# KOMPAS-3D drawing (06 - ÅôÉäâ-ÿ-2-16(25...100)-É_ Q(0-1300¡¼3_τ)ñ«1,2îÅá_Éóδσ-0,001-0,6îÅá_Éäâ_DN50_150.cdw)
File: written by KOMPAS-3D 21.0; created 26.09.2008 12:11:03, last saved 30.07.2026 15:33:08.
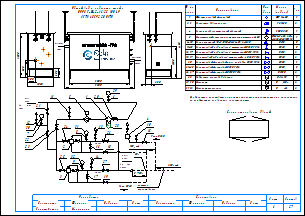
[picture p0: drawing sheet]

Sheets 1-2: A3, landscape

Document properties: Наименование: Макро:21; Автор: RaskoAdmin; Форматы листов документа: 2xA3; Полное имя файла: \\ur38nt01\Departments\КТО\КБ ПУРДГ\Заявки\Прайс-лист на типовые шкафы ГРПШ\ПУРДГ_стандарт_30_04_2026\ПУРДГ с РДГ(Н, В)\ПУРДГ-Ш-2-16(25...100)-Р_ Q(0-1300нм3_ч)до1,2МПа_Рвых-0,001-0,6МПа_РДГ_DN50_150.cdw

Title block, sheet 1: Наименование: Пункт учета газа / ПУГ-Ш-400-Р / ЛГТИ.485922.001ТУ; designation: ЛГТИ.03.4411141; sheet number: 1; Количество листов документа: 2; organisation: ООО "ЭЛЬСТЕР Газэлектроника"; Форматы листов документа: A3; stored path: C:\Рабочие документы\Компас\ПУГ\Схема.cdw; Разработал: Устинов; Проверил: Кошкин; Утвердил: Кошкин
Title block, sheet 2: sheet number: 2; stored path: D:\Рабочие документы\Заявки\ПУРДГ\ПУРДГ-ШУЭО-2-100-Р 4411220.cdw; designation, second copy: ЛГТИ.03.4411141-

Views: Вид 1, Вид 2
Referenced files: wcvoit.frw
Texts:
  Normal
  № на
  схеме
  Усл.
  обозн.
  Марка
  (модель)
  Кол.
  Фильтр газовый фланцевый
  ФГ 16-50
  Регулятор давления газа
  РДГ-50
  Клапан предохранительный сбросной
  КПС DN20
  Измерительный комплекс с ротационным счетчиком Ду50
  СГ-ЭК-Р-(0,2...2,0)-
  Кран кнопочный VE-РАСКО-НЗ-1,6-G1/2-М20
  DN15
  Кран шаровой "под приварку" штуцерный DN20 PN16
  DN20
  Кран шаровой "под приварку" штуцерный DN15 PN16
  Кран шаровой "под приварку" штуцерный п/п DN20 PN16
  Кран шаровой фланцевый с мех. приводом DN50 PN16
  Кран шаровой фланцевый DN50 PN16
  Кран шаровой фланцевый DN150 PN16
  DN50
  DN150
  Индикатор перепада давления
  Манометр
  Манометр-напоромер
  Delta 15
  0...     МПа
  0...     кПа
  Общий вид и габариты шкафа
  ПУРДГ-Ш-2-16(25...100)-Р
  Выход газа
  Вход газа
  logo-rasko-ge.png
  DN 1
  местное
  сопротивление
  Римп DN20
  Выход
  газа
  Р=     кПа
  Вход
  Р=       МПа
  PDI
  Схема открывания дверей
  Предприятие изготовитель может заменять комплектующие на аналогичные,
  не ухудшающие заявленных характеристик.
  Должность
  Конструктор
  Фамилия
  Подпись
  Дата
  Согласовано
  Максимкин
  Лист
  Листов
  POLYLINE_STYLE_0.18_RGB_0_0_0
  POLYLINE_STYLE_0.50_RGB_0_0_0
  POLYLINE_STYLE_0.34_RGB_0_0_0
  PHANTOM_RGB_0_0_0_SC_1_THICK_0.18
  K5LT_THIN_RGB_0_0_0_THICK_0.18
  K5LT32769_RGB_0_0_0_THICK_0.18
  K5LT12_RGB_0_0_0_SC_1_THICK_0.18
  K5LT_DASHED_RGB_0_0_0_SC_1_THICK_0.18
  ACISOTGL_RGB_0_0_0_SC_0.8_THICK_0.25
  CONTINUOUS_RGB_0_127_31_THICK_0.3
  CONTINUOUS_RGB_0_0_255_THICK_0.35
  CONTINUOUS_RGB_255_0_0_THICK_0.35
  POLYLINE_STYLE_0.25_RGB_0_0_0
  CONTINUOUS_RGB_0_0_0_THICK_0.5
  POLYLINE_STYLE_0.35_RGB_0_0_255
  CONTINUOUS_RGB_0_0_0_THICK_0.4
  CONTINUOUS_RGB_0_0_0_THICK_0.35
  НЕВИДИМАЯ_RGB_0_0_0_SC_0.3_THICK_0.25
  СONTINUOUS_RGB_0_0_0_THICK_0.25
  ОСЕВАЯ2_RGB_248_153_30_SC_0.3_THICK_0.25
  Без оформления
Dimensions and other numbers on the sheet: 1; 2, 3; 2; 4; 5; 6-10; 11-15; 16, 17; 18, 19; 20; 21-25; 26, 27; 28; 29, 30; 31, 32; 1500; 250; 300; 1050; 550; 305; 3000; 4130; 2000; 3300; 5,,,7DN 1; 7; 30; 12; 21; 22; 23; 11; 6; 29; 24; 31; 8; 13; 26; 18; 10; 15; 25; 32; 9; 3; 14; 27; 19; 16; 17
